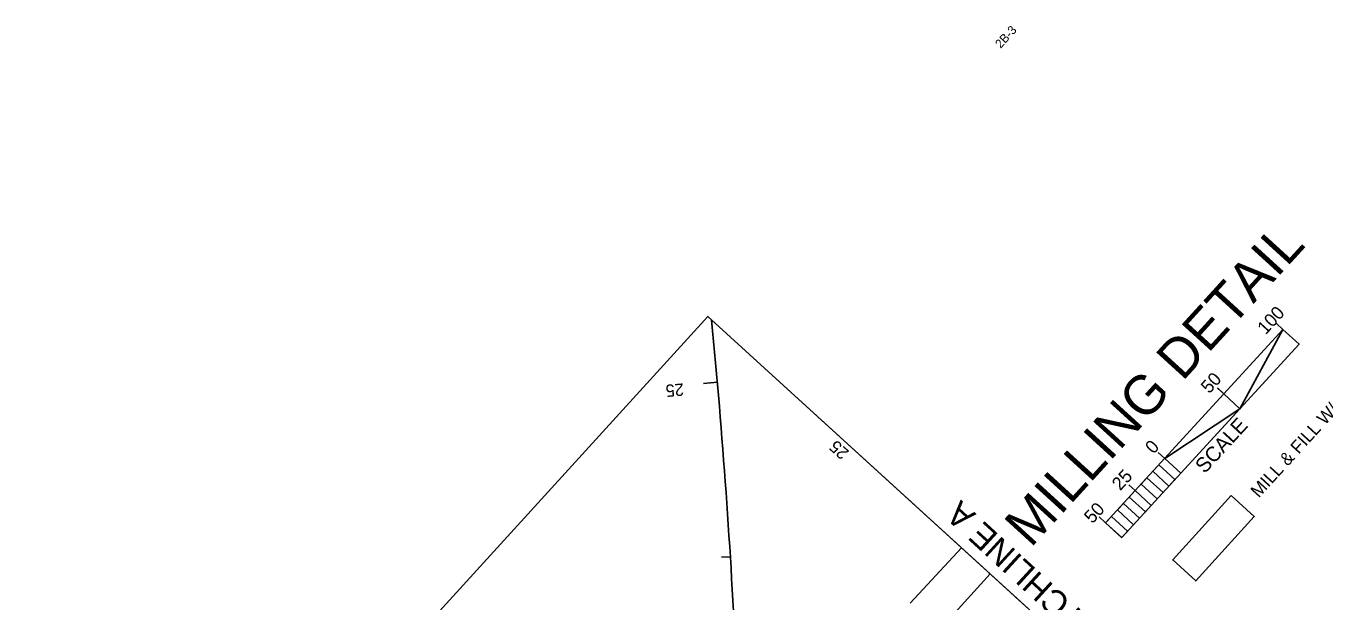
# Model space of a CAD drawing. Extents: x 1807040 to 1808827, y 913493 to 915218.
# Drawn here: x 1807478 to 1808221, y 914879 to 915208 of the extents above; entities that cross this region are included whole.
import ezdxf

# ---------------------------------------------------------------- set-up
doc = ezdxf.new("R2010")
doc.units = 0
for name, color, linetype in [('Matchline Text', 7, 'Continuous'), ('Old_Level_14', 7, 'Continuous'), ('Old_Level_40', 7, 'Continuous'), ('Old_Level_44', 7, 'Continuous'), ('Prop EOT', 7, 'Continuous'), ('Prop Horizontal Alignment Tick Label', 7, 'Continuous'), ('Prop Horizontal Alignment Tick Large', 7, 'Continuous'), ('Prop Horizontal Alignment Tick Small', 7, 'Continuous'), ('Prop Text', 7, 'Continuous'), ('Scratch_Level_0', 7, 'Continuous'), ('Scratch_Level_1', 7, 'Continuous'), ('Scratch_Level_3', 7, 'Continuous'), ('Sheet Data Field CELL', 7, 'Continuous'), ('Sheet Data Text CELL', 7, 'Continuous'), ('Sheet Title CELL', 7, 'Continuous')]:
    doc.layers.add(name, color=color, linetype=linetype)

msp = doc.modelspace()

# ---------------------------------------------------------------- linework, layer by layer
at = {"layer": 'Old_Level_14'}
msp.add_line((1807868.25, 915042.04), (1808256.27, 914688.39), dxfattribs=at)
at = {"layer": 'Old_Level_40'}
msp.add_lwpolyline([(1808167.51, 914939.65), (1808134.04, 914902.93), (1808147.19, 914890.95), (1808180.66, 914927.67)], close=True, dxfattribs=at)
at = {"layer": 'Prop EOT'}
msp.add_line((1807702.96, 914536.44), (1808029.68, 914894.91), dxfattribs=at)
msp.add_lwpolyline([(1807983.87, 914878.11), (1808013.34, 914909.8)], dxfattribs=at)
at = {"layer": 'Prop Horizontal Alignment Tick Large'}
for p, q in [((1807873.65, 915004.45), (1807865.68, 915003.75)), ((1808046.68, 914879.41), (1808040.76, 914884.8))]:
    msp.add_line(p, q, dxfattribs=at)
at = {"layer": 'Prop Horizontal Alignment Tick Small'}
msp.add_line((1807881.07, 914904.73), (1807876.08, 914904.42), dxfattribs=at)
at = {"layer": 'Scratch_Level_0'}
for p, q in [((1808029.68, 914894.91), (1808013.34, 914909.8)), ((1807702.96, 914536.44), (1808029.68, 914894.91))]:
    msp.add_line(p, q, dxfattribs=at)
for points in [[(1808167.51, 914939.65), (1808134.04, 914902.93), (1808147.19, 914890.95), (1808180.66, 914927.67), (1808167.51, 914939.65)], [(1808013.34, 914909.8), (1807983.87, 914878.11)]]:
    msp.add_lwpolyline(points, dxfattribs=at)
at = {"layer": 'Scratch_Level_1'}
msp.add_lwpolyline([(1807040.33, 914133.66), (1807040.33, 914133.66), (1807428.35, 913780.01), (1808256.27, 914688.39), (1807868.25, 915042.04)], close=True, dxfattribs=at)
at = {"layer": 'Scratch_Level_3'}
msp.add_arc((1803888.72, 914657.58), 4000, 2.65322, 5.4874, dxfattribs=at)
at = {"layer": 'Sheet Data Field CELL'}
for p, q in [((1808197.09, 915034.63), (1808193.4, 915038.02)), ((1808163.28, 914997.79), (1808159.61, 915001.17)), ((1808112.59, 914942.52), (1808108.9, 914945.9)), ((1808095.68, 914924.11), (1808092, 914927.48)), ((1808095.68, 914924.09), (1808092, 914927.46))]:
    msp.add_line(p, q, dxfattribs=at)
at = {"layer": 'Sheet Title CELL'}
for p, q in [((1808197.09, 915034.62), (1808095.68, 914924.09)), ((1808197.09, 915034.62), (1808193.4, 915038)), ((1808206.31, 915026.16), (1808197.09, 915034.62)), ((1808104.89, 914915.64), (1808206.31, 915026.16)), ((1808163.28, 914997.78), (1808159.61, 915001.15)), ((1808163.28, 914997.78), (1808172.49, 914989.33)), ((1808129.49, 914960.93), (1808125.81, 914964.31)), ((1808112.59, 914942.5), (1808108.9, 914945.89)), ((1808119.34, 914949.88), (1808128.55, 914941.43)), ((1808095.68, 914924.09), (1808092, 914927.46)), ((1808092, 914927.46), (1808092, 914927.46)), ((1808095.68, 914924.07), (1808092, 914927.45)), ((1808092, 914927.45), (1808092, 914927.45)), ((1808095.68, 914924.09), (1808104.89, 914915.64)), ((1808095.68, 914924.09), (1808095.68, 914924.09)), ((1808095.68, 914924.07), (1808104.89, 914915.62)), ((1808095.68, 914924.07), (1808095.68, 914924.07))]:
    msp.add_line(p, q, dxfattribs=at)
for points in [[(1808197.09, 915034.62), (1808172.49, 914989.33), (1808206.31, 915026.16)], [(1808129.49, 914960.93), (1808172.49, 914989.33), (1808138.7, 914952.48)], [(1808122.72, 914953.57), (1808126.1, 914957.25), (1808135.32, 914948.79), (1808131.93, 914945.12)], [(1808115.97, 914946.19), (1808119.34, 914949.88), (1808128.55, 914941.43), (1808125.17, 914937.75)], [(1808109.21, 914938.82), (1808112.59, 914942.5), (1808121.79, 914934.06), (1808118.41, 914930.38)], [(1808102.44, 914931.46), (1808105.83, 914935.14), (1808115.04, 914926.69), (1808111.67, 914923.01)], [(1808095.68, 914924.09), (1808099.06, 914927.78), (1808108.27, 914919.33), (1808104.89, 914915.64)]]:
    msp.add_lwpolyline(points, close=True, dxfattribs=at)

# ---------------------------------------------------------------- texts
at = {"layer": 'Matchline Text'}
msp.add_text('MATCHLINE A', height=14, rotation=137.47907, dxfattribs=at).set_placement((1808105.58, 914852.44))
at = {"layer": 'Old_Level_44'}
msp.add_text('2B-3', height=5, rotation=47.65322, dxfattribs=at).set_placement((1808035.69, 915195.01))
at = {"layer": 'Prop Horizontal Alignment Tick Label'}
for rotation, p in [(184.97471, (1807854.19, 915003.85)), (137.65322, (1807949.41, 914964.83))]:
    msp.add_text('25', height=7, rotation=rotation, dxfattribs=at).set_placement(p)
at = {"layer": 'Prop Text'}
msp.add_text('MILL & FILL W/  UBWC', height=7.35, rotation=47.65323, dxfattribs=at).set_placement((1808183.28, 914937.96))
at = {"layer": 'Sheet Data Text CELL'}
msp.add_text('MILLING DETAIL', height=22.5, rotation=47.65322, dxfattribs=at).set_placement((1808052.89, 914909.39))
at = {"layer": 'Sheet Title CELL'}
for s, height, p in [('100', 7.5, (1808187.25, 915031.3)), ('50', 7.5, (1808154.96, 914997.58)), ('SCALE', 8.5, (1808152.38, 914951.85)), ('0', 7.5, (1808123.1, 914963.06)), ('25', 7.5, (1808104.06, 914942.11)), ('50', 7.5, (1808088.14, 914923.26))]:
    msp.add_text(s, height=height, rotation=47.46423, dxfattribs=at).set_placement(p)

doc.saveas('drawing.dxf')
